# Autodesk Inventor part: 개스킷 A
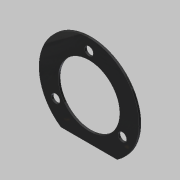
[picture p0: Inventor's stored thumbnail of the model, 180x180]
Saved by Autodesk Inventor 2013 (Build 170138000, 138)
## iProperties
Created: 2020-04
Part Number: 개스킷 A
Material: 고무
Document SubType Name: Modeling
Designer: mduedu
Density: 1 g/cm^3
Author: mduedu
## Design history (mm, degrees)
sketch "스케치1"
  geometry: C1 r 26 at (0, 0); 1 further point
  constraints: 1 centre point, 1 coincident
  dimensions: "d0" = 52 diameter of C1
extrude "돌출1" new body sketch "스케치1" distance "d1" = 1; taper "d2" = 0 deg
sketch "스케치2"
  geometry: L1 (-14.62, -21.5)-(14.62, -21.5); A1 r 26 centre (0, 0) between (-14.62, -21.5) and (14.62, -21.5) reference; 1 further point
  constraints: 2 end point, 2 point on circle, 1 horizontal
  dimensions: "d3" = 21.5 distance from line of L1 point (0, 0)
extrude "돌출2" cut sketch "스케치2" stored distance "d4" = 1; taper "d5" = 0 deg
sketch "스케치3" dims "d6" = 40
  geometry: 3 further points
  constraints: 2 vertical alignment, 1 coincident, 2 other
hole "구멍1" sketch "스케치3" at (0, 20) diameter "d7" = 4.5; stored, may be unused: countersink angle "d11" = 90 deg, drill point angle "d13" = 118 deg; dims "d8" = 6, "d9" = 4, "d10" = 2, "d12" = 8
sketch "스케치4"
  geometry: C1 r 16 at (0, 0); 1 further point
  constraints: 1 centre point, 1 coincident
  dimensions: "d17" = 32 diameter of C1
extrude "돌출3" cut sketch "스케치4" stored distance "d18" = 1; taper "d19" = 0 deg
node "솔리드1"
pattern_circular "원형 패턴1" dims angle "d15" = 360 deg
node "투영된 루프1"
